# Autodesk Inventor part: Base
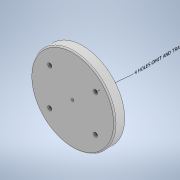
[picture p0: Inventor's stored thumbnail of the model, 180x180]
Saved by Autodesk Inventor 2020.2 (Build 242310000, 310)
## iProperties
Created: 2019-12
Part Number: Base
Material: Generic
Document SubType Name: Modeling
Designer: Patrick Everitt
Density: 1 g/cm^3
Appearance: Default
Description: 8 1/2 Dia x 1 1/8 Lng
Author: Patrick Everitt
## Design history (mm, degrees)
node "Annotations"
  node "Leader Text 1"
sketch "Sketch1"
  geometry: C1 r 107.95 at (0, 0); 1 further point
  constraints: 1 centre point, 1 coincident
  dimensions: "d0" = 215.9 diameter of C1
extrude "Extrusion1" new body sketch "Sketch1" distance "d1" = 25.4; taper "d2" = 0 deg
sketch "Sketch2"
  geometry: 2 further points
  constraints: 1 coincident
hole "Hole1" sketch "Sketch2" at (0, 0) diameter "d3" = 6.35; stored, may be unused: countersink angle "d7" = 82 deg, drill point angle "d9" = 118 deg; dims "d4" = 19.05, "d5" = 9.525, "d6" = 6.35, "d8" = 25.4
fillet "Fillet2" dims "d14" = 3.175
sketch "Sketch4"
  geometry: C1 r 3.175 at (0, 0) reference; 5 further points
  dimensions: "d30" = 58.7375 horizontal distance of C1.centre point (-58.738, 47.625); "d31" = 47.625 vertical distance of point (0, 0) point (-58.738, 47.625); "d32" = 58.7375 horizontal distance of point (0, 0) point (58.738, 47.625) (= d30); "d33" = 47.625 vertical distance of point (0, 0) point (58.738, 47.625) (= d31); "d34" = 47.625 vertical distance of point (0, 0) point (58.738, -47.625) (= d31); "d35" = 58.7375 horizontal distance of C1.centre point (58.738, -47.625) (= d30); "d36" = 58.7375 horizontal distance of point (0, 0) point (-58.738, -47.625) (= d30); "d37" = 47.625 vertical distance of point (0, 0) point (-58.738, -47.625) (= d31)
hole "Hole3" sketch "Sketch4" at (-58.738, -47.625), (-58.738, 47.625), (58.738, 47.625), (58.738, -47.625) diameter "d38" = 10.3124; stored, may be unused: countersink angle "d42" = 82 deg, drill point angle "d44" = 118 deg; dims "d39" = 19.05, "d40" = 15.0876, "d41" = 10.3124, "d43" = 25.4
body "Solid1"
other parameters: "d45" = 8.24615 (derived), "d46" = 7.64763 (derived)
